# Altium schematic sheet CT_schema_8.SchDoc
size 278 x 170 mm
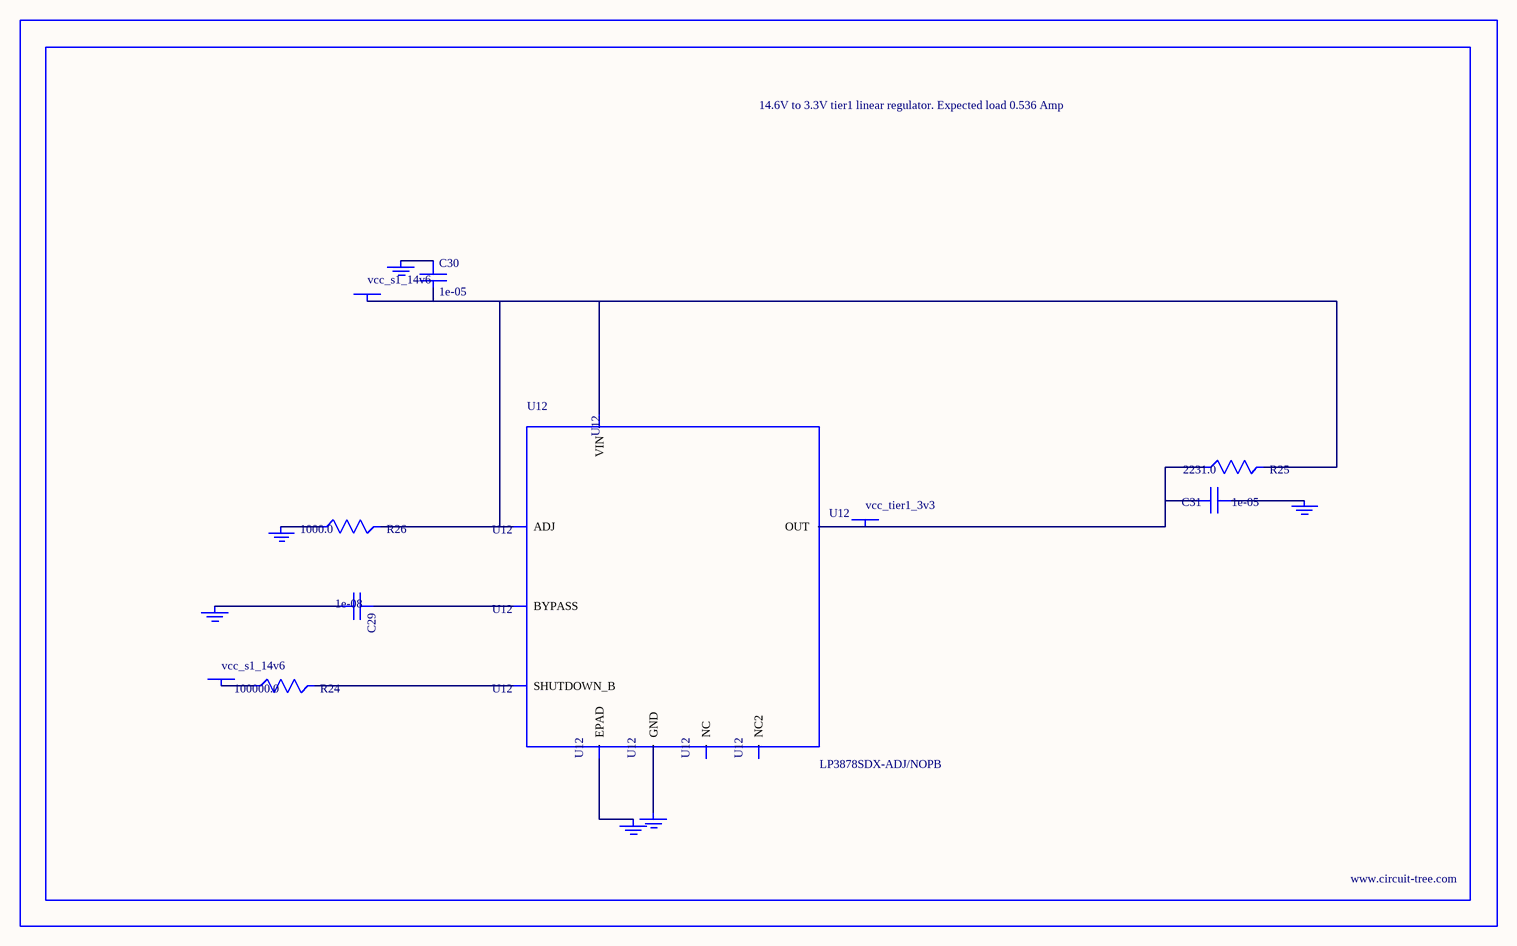
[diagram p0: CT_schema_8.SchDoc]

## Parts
BORDER7  (no value)
C29  1e-08  [C0402]
C30  1e-05  [C1210]
C31  1e-05  [C1210]
GND_INSTANCE_7_0  (no value)
GND_INSTANCE_7_1  (no value)
GND_INSTANCE_7_2  (no value)
GND_INSTANCE_7_3  (no value)
GND_INSTANCE_7_4  (no value)
GND_INSTANCE_7_5  (no value)
POWER_INSTANCE_7_0  vcc_s1_14v6
POWER_INSTANCE_7_1  vcc_s1_14v6
POWER_INSTANCE_7_2  vcc_tier1_3v3
R24  100000.0  [R0603]
R25  2231.0  [R0603]
R26  1000.0  [R0603]
U12  LP3878SDX-ADJ/NOPB  [WSON-8]

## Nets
NetC29_1: C29.1 U12.1(BYPASS)
NetC29_2: C29.2 GND_INSTANCE_7_0.0(GND)
NetC30_1: C30.1 GND_INSTANCE_7_1.0(GND)
NetC30_2: C30.2 POWER_INSTANCE_7_0.0(PWR) R25.2 R26.2 U12.4(VIN) U12.6(ADJ)
NetC31_1: C31.1 GND_INSTANCE_7_2.0(GND)
NetC31_2: C31.2 POWER_INSTANCE_7_2.0(PWR) R25.1 U12.5(OUT)
NetGND_INSTANCE_7_3_0: GND_INSTANCE_7_3.0(GND) R26.1
NetGND_INSTANCE_7_4_0: GND_INSTANCE_7_4.0(GND) U12.PAD(EPAD)
NetGND_INSTANCE_7_5_0: GND_INSTANCE_7_5.0(GND) U12.3(GND)
NetPOWER_INSTANCE_7_1_0: POWER_INSTANCE_7_1.0(PWR) R24.1
NetR24_2: R24.2 U12.8(SHUTDOWN_B)

Not connected (* = marked no-connect by the designer): U12 2(NC) 7(NC2)

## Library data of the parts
BORDER7 = BORDER_PAGE7
C29 = C0402C103K3RAC
C30 = C1210C106K5PACTU
C31 = GRM32DR61E106MA12L
GND_INSTANCE_7_0-GND_INSTANCE_7_5 = GND
POWER_INSTANCE_7_0-POWER_INSTANCE_7_2 = PWR
R24 = RC0603JR-07100KL
R25 = R25
R26 = RC0603JR-071KL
